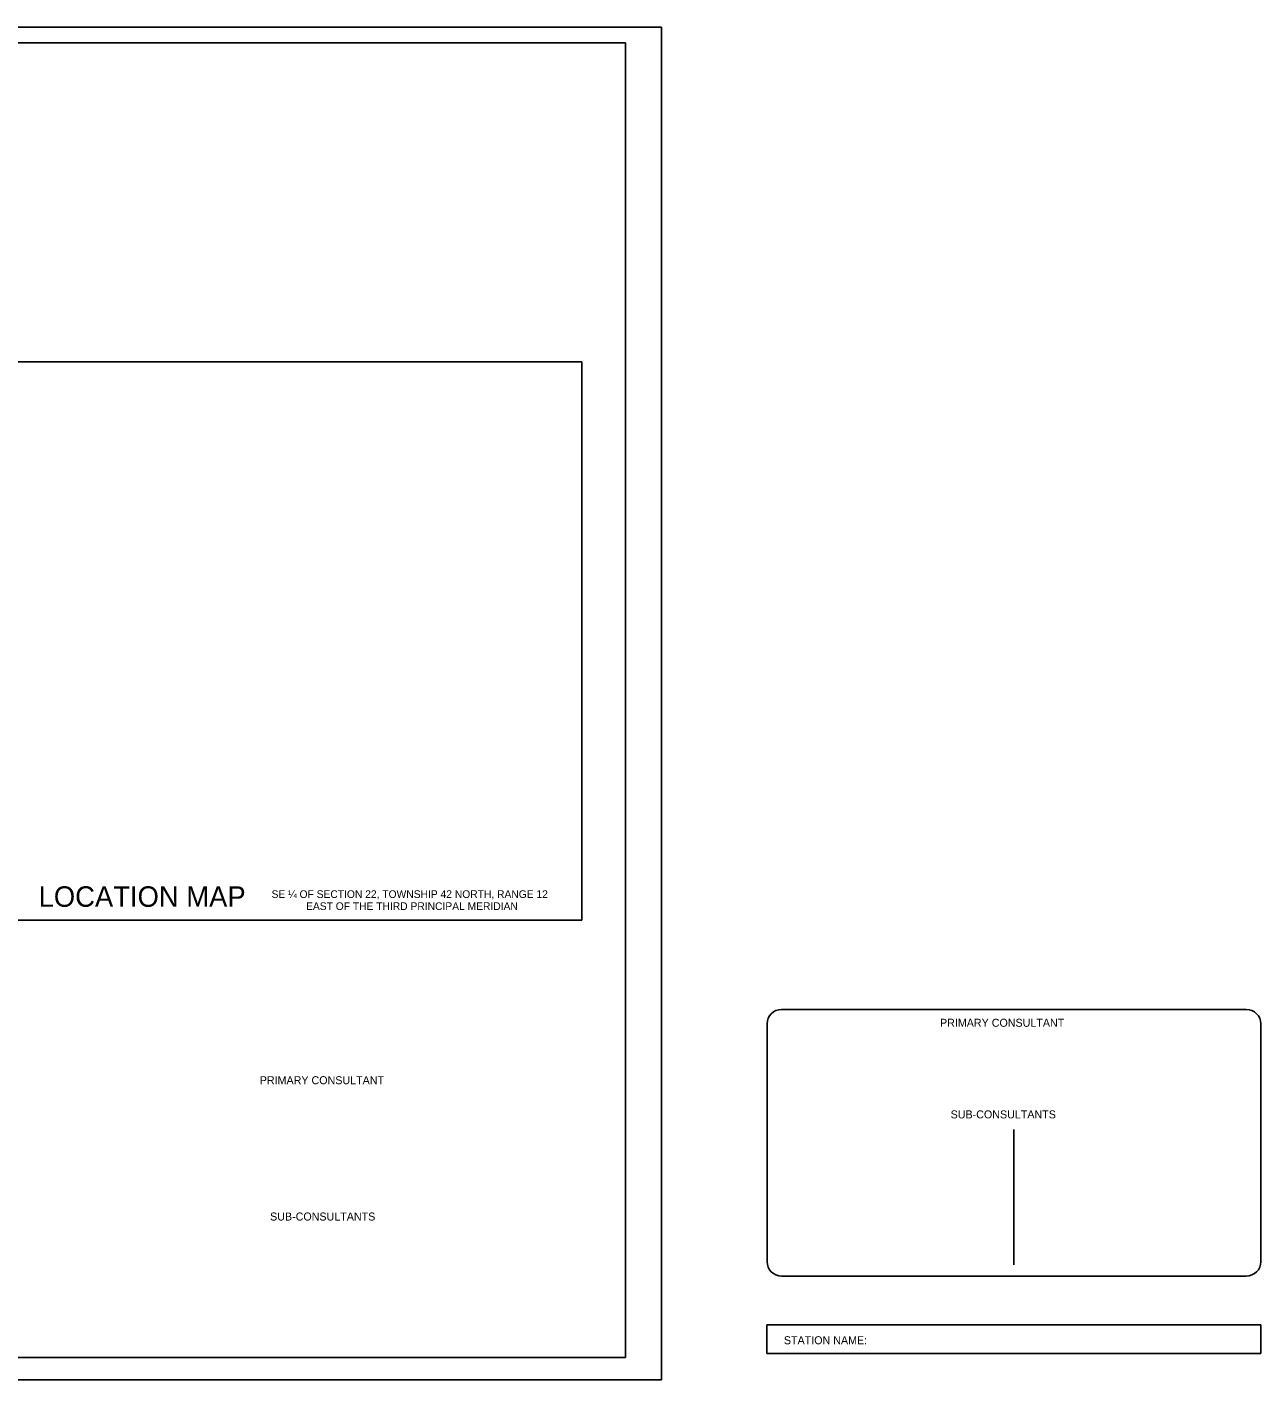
# Model space of a CAD drawing. Extents: x 46.6 to 90.4, y 0.3 to 22.3.
# Drawn here: x 70.28 to 90.36, y 0.26 to 22.28 of the extents above; entities that cross this region are included whole.
import ezdxf

# ---------------------------------------------------------------- set-up
doc = ezdxf.new("R2010")
doc.units = 0
doc.layers.add('A-Text', color=7, linetype='Continuous')
doc.layers.add('Level 1', color=7, linetype='Continuous')

msp = doc.modelspace()

# ---------------------------------------------------------------- linework, layer by layer
at = {"layer": 'Level 1'}
for p, q in [((80.605, 22.275), (46.583, 22.275)), ((80.605, 0.261), (80.605, 22.275)), ((80.019, 22.019), (47.876, 22.019)), ((80.019, 0.629), (80.019, 22.019)), ((90.118, 6.288), (82.559, 6.288)), ((82.321, 6.056), (82.321, 2.184)), ((90.356, 6.056), (90.356, 2.184)), ((86.337, 4.339), (86.337, 2.133)), ((90.118, 1.951), (82.561, 1.951)), ((90.353, 1.159), (82.317, 1.159)), ((82.317, 1.159), (82.317, 0.694)), ((90.353, 1.159), (90.353, 0.694)), ((90.353, 0.694), (82.317, 0.694)), ((80.019, 0.629), (47.876, 0.629)), ((46.583, 0.261), (80.605, 0.261))]:
    msp.add_line(p, q, dxfattribs=at)
for points in [[(79.306, 16.83), (69.899, 16.83), (69.899, 7.74), (79.306, 7.74)], [(79.306, 7.74), (79.306, 16.83)]]:
    msp.add_lwpolyline(points, dxfattribs=at)
for centre, major_axis, start_param, end_param in [((82.559, 6.056), (-0.238, 0), 4.712389, 6.283185), ((90.118, 6.056), (-0.238, 0), 3.141593, 4.712389), ((82.559, 2.184), (-0.238, 0), 0, 1.570796), ((90.118, 2.184), (0.238, 0), 4.712389, 6.283185)]:
    msp.add_ellipse(centre, major_axis=major_axis, ratio=0.976508, start_param=start_param, end_param=end_param, dxfattribs=at)

# ---------------------------------------------------------------- texts
at = {"layer": 'A-Text'}
for s, p in [('SE ¼ OF SECTION 22, TOWNSHIP 42 NORTH, RANGE 12 ', (74.26, 8.104)), ('EAST OF THE THIRD PRINCIPAL MERIDIAN', (74.821, 7.908))]:
    msp.add_text(s, height=0.125, dxfattribs=at).set_placement(p)
at = {"layer": 'Level 1'}
for s, height, p in [('LOCATION MAP', 0.33333, (70.47, 7.96)), ('PRIMARY CONSULTANT', 0.1302, (85.135, 6.008)), ('PRIMARY CONSULTANT', 0.1302, (74.068, 5.073)), ('SUB-CONSULTANTS', 0.1302, (85.308, 4.517)), ('SUB-CONSULTANTS', 0.1302, (74.236, 2.855)), ('STATION NAME: ', 0.1302, (82.595, 0.842))]:
    msp.add_text(s, height=height, dxfattribs=at).set_placement(p)

doc.saveas('drawing.dxf')
